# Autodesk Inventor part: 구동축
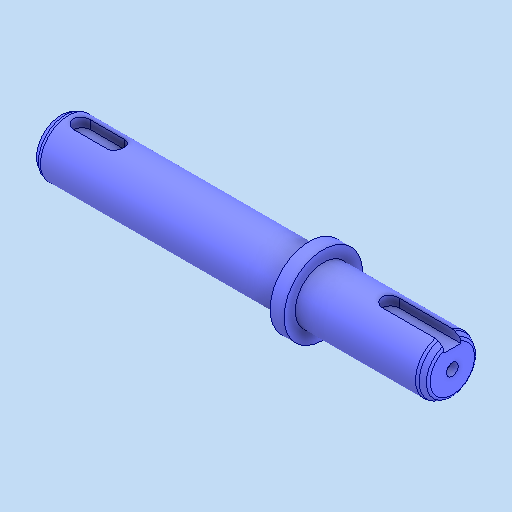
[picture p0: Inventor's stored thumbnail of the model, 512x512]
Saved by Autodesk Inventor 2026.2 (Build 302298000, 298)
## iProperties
Created: 2026-01
Part Number: 구동축
Material: 강철, 탄소
Document SubType Name: Modeling
Designer: PC2-07
Density: 7.85 g/cm^3
Appearance: 기본값
Author: jhkim
Sending System: Autodesk Inventor 2026
Preprocessor: ST-DEVELOPER v20.1
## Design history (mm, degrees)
feature "솔리드1"
node "솔리드2"
